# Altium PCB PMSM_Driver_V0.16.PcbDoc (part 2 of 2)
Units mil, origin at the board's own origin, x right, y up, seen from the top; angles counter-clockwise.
Board outline 3933.5 x 3936.3 mil, 2 copper layers (Top Layer, Bottom Layer); 174 components, 117 nets, 508 pads, 484 vias.
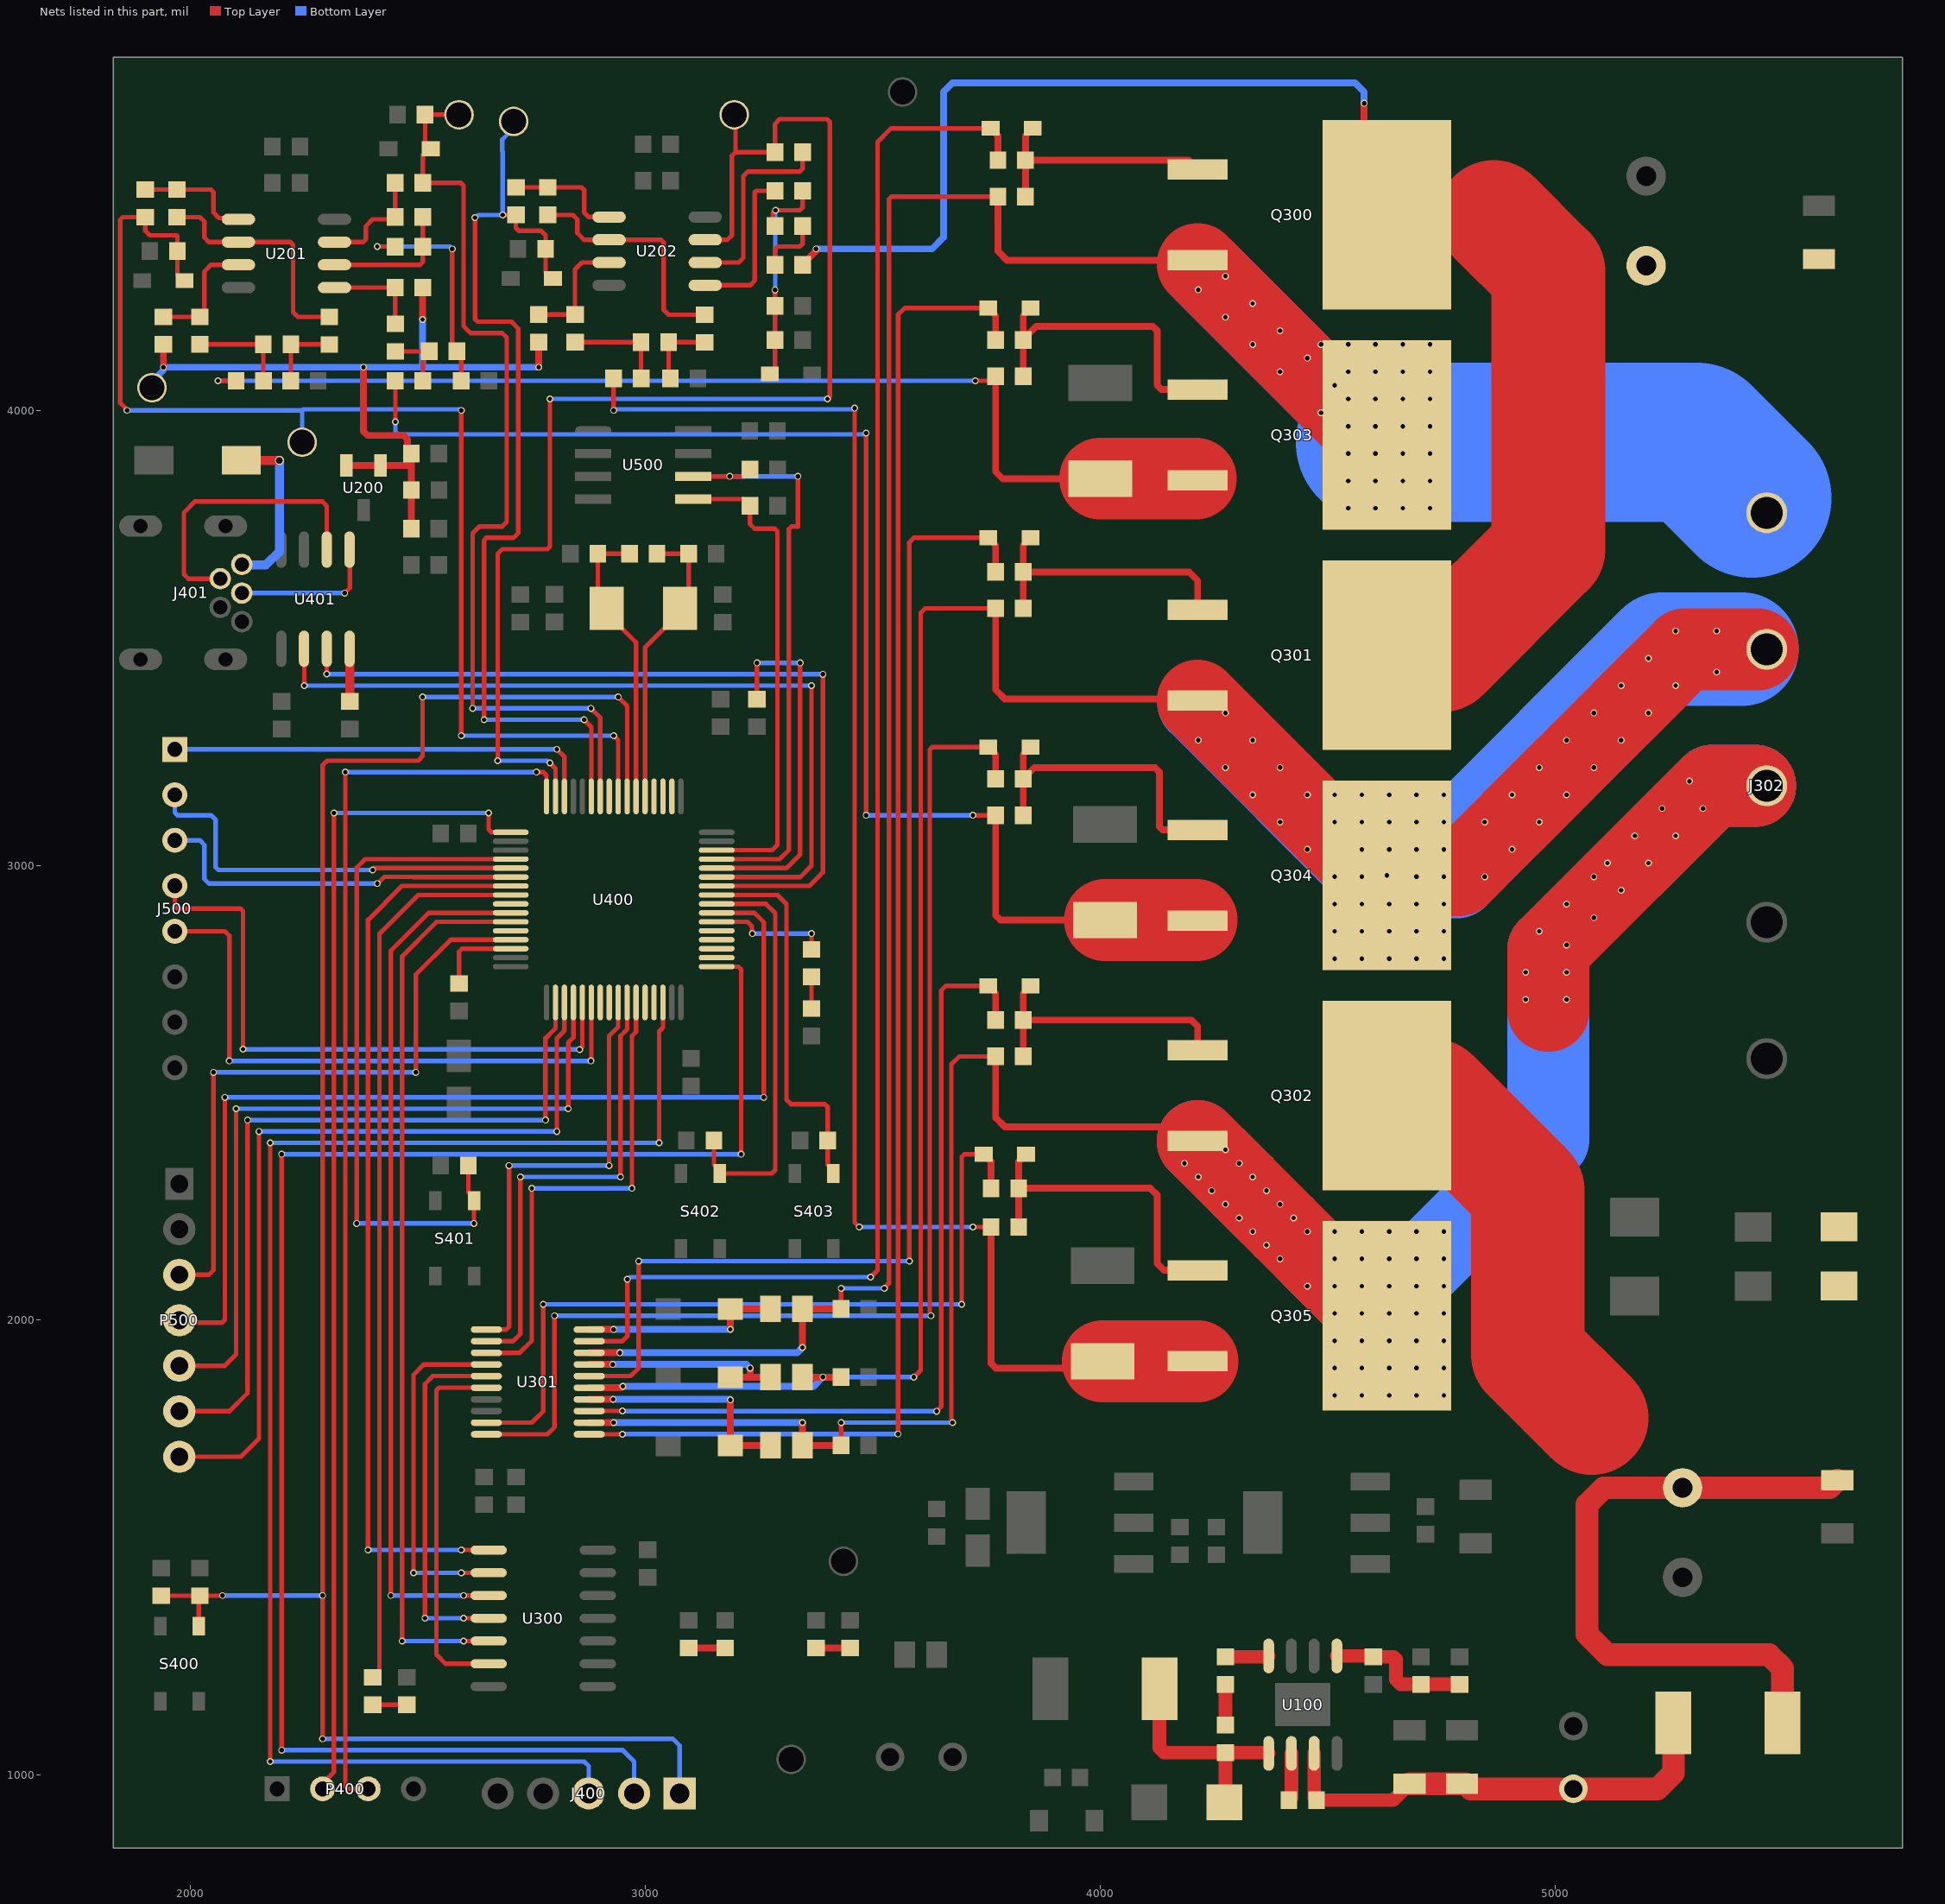
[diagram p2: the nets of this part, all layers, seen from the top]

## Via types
v1: diameter 15, hole 10, Top Layer to Bottom Layer, 465 vias
v2: diameter 30, hole 25, Top Layer to Bottom Layer, 11 vias
v3: diameter 24, hole 12, Top Layer to Bottom Layer, 4 vias
v4: diameter 20, hole 15, Top Layer to Bottom Layer, 3 vias
v5: diameter 30, hole 20, Top Layer to Bottom Layer, 1 vias

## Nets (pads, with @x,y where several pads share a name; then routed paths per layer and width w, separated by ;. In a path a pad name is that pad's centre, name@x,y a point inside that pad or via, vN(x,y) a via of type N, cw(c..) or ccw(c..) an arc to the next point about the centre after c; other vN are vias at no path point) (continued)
EG-VS1: C304.2 J302.1 Q300.3 Q303.4 R303.1 R306.2 U301.18 | length 5971.6
  Top Layer w10: R306.2@3429.68,2025 3429.68,2069.68 v1(3430,2070) ; v1(3525,2070) 3525,2071.35 3535,2081.35 3535,4464.14 3540.86,4470 R303.1@3774.69,4470
  Top Layer w15: U301.18@2876.06,1928.54 v1(2943.54,1928.54) ; v1(3345,1940) v1(3345,1940) C304.2@3345.04,2025 R306.2@3429.68,2025 ; R303.1@3774.69,4470 3774.69,4350.31 3795,4330 Q300.3@4213.8,4330
  Top Layer w180: Q300.3@4213.8,4321.2 4589,3946 Q303.4@4630,3946
  Bottom Layer w10: v1(3430,2070) v1(3525,2070)
  Bottom Layer w15: v1(2943.54,1928.54) 3333.54,1928.54 v1(3345,1940)
  Bottom Layer w180: 4229.8,4305.2 4605,3930
  Bottom Layer w350: 4605,3930 5310,3930 5432.5,3807.5
  other v1: 4545,3785 4605,3785 4665,3785 4725,3785 4545,3845 4605,3845 4665,3845 4725,3845 4545,3905 4605,3905 4665,3905 4725,3905 4545,3965 4605,3965 4665,3965 4725,3965 4485,3995 4545,4025 4605,4025 4665,4025 4725,4025 4515,4055 4395,4085 4545,4085 4605,4085 4665,4085 4725,4085 4455,4115 4335,4145 4485,4145 4545,4145 4605,4145 4665,4145 4725,4145 4395,4175 4275,4205 4335,4235 4215,4265 4275,4295
EG-VS2: C306.2 J302.2 Q301.3 Q304.4 R304.1 R307.2 U301.15 | length 6433.2
  Top Layer w10: v1(3590,1875) 3605,1890 3605,3555 3615,3565 R304.1@3769.69,3565
  Top Layer w15: U301.15@2876.06,1851.77 2946.91,1851.77 v1(2950,1854.86) ; C306.2@3345.04,1875 v1(3390,1875) R307.2@3429.68,1875 ; R304.1@3769.69,3565 3769.69,3386.12 3790,3365.8 4210,3365.8 Q301.3@4213.8,3362
  Top Layer w180: Q301.3@4213.8,3362 4317.9,3257.9 4377.9,3197.9 4437.9,3137.9 4497.9,3077.9 4597.8,2978 v1(4630,2978) 4695,2978 4788,2978 4875,3065 4935,3125 4995,3185 5055,3245 5115,3305 5175,3365 5285,3475 J302.2@5445,3475
  Bottom Layer w10: v1(3390,1875) v1(3590,1875)
  Bottom Layer w15: v1(2950,1854.86) 3369.86,1854.86 v1(3390,1875)
  Bottom Layer w180: 4215.02,3357.98 4599.02,2973.98 4783.98,2973.98
  Bottom Layer w250: 4783.98,3023.98 5235,3475 5410,3475
  other v1: 4515,2795 4575,2795 4635,2795 4695,2795 4755,2795 4515,2855 4575,2855 4635,2855 4695,2855 4755,2855 4515,2915 4575,2915 4635,2915 4695,2915 4755,2915 4515,2975 4575,2975 4695,2975 4755,2975 4845,2975 4455,3035 4575,3035 4635,3035 4695,3035 4755,3035 4905,3035 4395,3095 4515,3095 4575,3095 4635,3095 4695,3095 4755,3095 4845,3095 4965,3095 4335,3155 4455,3155 4515,3155 4575,3155 4635,3155 4695,3155 4755,3155 4905,3155 5025,3155 4275,3215 4395,3215 4965,3215 5085,3215 4215,3275 4335,3275 5025,3275 5145,3275 4275,3335 5085,3335 5205,3335 5145,3395 5265,3395 5355,3425 5205,3455 5265,3515 5355,3515
EG-VS3: C307.2 J302.3 Q302.3 Q305.4 R305.1 R308.2 U301.12 | length 5818.7
  Top Layer w10: R308.2@3429.68,1725 3429.68,1774.68 v1(3430,1775) ; v1(3675,1775) 3672.5,1777.5 3672.5,2562.5 3690,2580 R305.1@3769.69,2580
  Top Layer w15: U301.12@2876.06,1775 v1(2930,1775) ; v1(3345,1775) C307.2@3345.04,1725 C307.2@3345.04,1725 R308.2@3429.68,1725 ; R305.1@3769.69,2580 3769.69,2445.31 3790,2425 4182.8,2425 Q302.3@4213.8,2394
  Top Layer w180: Q302.3@4213.8,2394 4283.9,2323.9 4343.9,2263.9 4403.9,2203.9 4493.9,2113.9 4597.8,2010 Q305.4@4630,2010 ; 4985,2680 4985,2815 5345,3175 J302.3@5440,3175
  Bottom Layer w10: v1(3430,1775) v1(3675,1775)
  Bottom Layer w15: v1(2930,1775) v1(3345,1775)
  Bottom Layer w180: 4213.8,2394 4253.9,2353.9 4313.9,2293.9 4403.9,2203.9 4523.9,2083.9 4597.8,2010 4985,2397.2 4985,2815 5345,3175 J302.3@5440,3175
  other v1: 4515,1835 4575,1835 4635,1835 4695,1835 4755,1835 4515,1895 4575,1895 4635,1895 4695,1895 4755,1895 4515,1955 4575,1955 4635,1955 4695,1955 4755,1955 4515,2015 4575,2015 4635,2015 4695,2015 4755,2015 4455,2075 4515,2075 4575,2075 4635,2075 4695,2075 4755,2075 4395,2135 4515,2135 4575,2135 4635,2135 4695,2135 4755,2135 4365,2165 4335,2195 4455,2195 4515,2195 4575,2195 4635,2195 4695,2195 4755,2195 4305,2225 4425,2225 4275,2255 4395,2255 4245,2285 4365,2285 4215,2315 4335,2315 4185,2345 4305,2345 4275,2375 4935,2705 5025,2705 4935,2765 5025,2765 5025,2825 4965,2855 5085,2885 5025,2915 5145,2945 5085,2975 5115,3005 5205,3005 5175,3065 5265,3065 5235,3125 5325,3125 5295,3185
HO1: D300.2 R300.1 U301.19 | length 3589.4
  Top Layer w10: U301.19@2876.06,1954.13 2949.13,1954.13 2960,1965 v1(2960,2090) ; v1(3495,2095) 3510,2110 3510,4590 3540,4620 D300.2@3758.54,4620
  Top Layer w15: D300.2@3758.54,4620 3774.69,4603.86 R300.1@3774.69,4550
  Bottom Layer w10: v1(2960,2090) 2961.35,2090 2966.35,2095 v1(3495,2095)
HO2: D301.2 R301.1 U301.16 | length 2785.6
  Top Layer w10: U301.16@2876.06,1877.36 2940.54,1877.36 2940.61,1877.43 2967.43,1877.43 2985,1895 v1(2985,2130) ; v1(3580,2130) 3580,3710 3590,3720 D301.2@3753.54,3720
  Top Layer w15: D301.2@3753.54,3720 3769.69,3703.86 R301.1@3769.69,3645
  Bottom Layer w10: v1(2985,2130) v1(3580,2130)
HO3: D302.2 R302.1 U301.13 | length 1882.7
  Top Layer w10: U301.13@2876.06,1800.59 v1(2949.41,1800.59) ; v1(3640,1800) 3650,1810 3650,2725 3660,2735 D302.2@3753.54,2735
  Top Layer w15: D302.2@3753.54,2735 3769.69,2718.86 R302.1@3769.69,2660
  Bottom Layer w10: v1(2949.41,1800.59) 2950,1800 v1(3640,1800)
HSE_IN: C400.2 OSC400.1 R401.1 U400.5 | length 642.7
  Top Layer w10: U400.5@2998.9,3151.37 2998.9,3478.34 3075.71,3555.15 OSC400.1@3075.71,3564.99 3094.68,3583.97 C400.2@3094.68,3685 R401.1@3025.31,3685
HSE_OUT: C401.2 OSC400.2 R401.2 U400.6 | length 637.7
  Top Layer w10: R401.2@2964.68,3685 C401.2@2895.32,3685 2895.32,3583.97 OSC400.2@2914.29,3564.99 2914.29,3555.15 2979.21,3490.23 U400.6@2979.21,3151.37
LO1: D303.2 R309.1 U301.11 | length 3420.6
  Top Layer w10: U301.11@2876.06,1749.41 v1(2949.41,1749.41) ; v1(3555,1750) 3555,4210 3570,4225 D303.2@3753.54,4225
  Top Layer w15: D303.2@3753.54,4225 3769.69,4208.86 R309.1@3769.69,4155
  Bottom Layer w10: v1(2949.41,1749.41) 2950,1750 v1(3555,1750)
LO2: D304.2 R310.1 U301.10 | length 2681.8
  Top Layer w10: U301.10@2650,1749.41 2784.41,1749.41 2800,1765 v1(2800,2010) ; v1(3627.5,2010) 3625,2012.5 3625,3254.14 3630.86,3260 D304.2@3753.54,3260
  Top Layer w15: D304.2@3753.54,3260 3769.69,3243.86 R310.1@3769.69,3190
  Bottom Layer w10: v1(2800,2010) v1(3627.5,2010)
LO3: D305.2 R311.1 U301.9 | length 1747.2
  Top Layer w10: U301.9@2650,1775 2750,1775 2775,1800 v1(2775,2035) ; v1(3695,2035) 3695,2359.14 3700.86,2365 D305.2@3743.54,2365
  Top Layer w15: D305.2@3743.54,2365 3759.69,2348.86 R311.1@3759.69,2290
  Bottom Layer w10: v1(2775,2035) v1(3695,2035)
MOTOR_AMP-U: Q303.3 R209.1 R312.1 R315.2 | length 2401.2
  Top Layer w10: v1(2060,4065) R209.1@2099.69,4065 ; v1(3725,4065) R312.1@3769.69,4065
  Top Layer w15: R312.1@3769.69,4065 3769.69,3865.31 3785,3850 R315.2@4000,3850 ; Q303.3@4209.8,3850 Q303.3@4213.8,3846
  Top Layer w180: R315.2@4000,3850 Q303.3@4209.8,3850
  Bottom Layer w10: v1(2060,4065) v1(3725,4065)
MOTOR_AMP-V: Q304.3 R211.1 R313.1 R316.2 | length 2943.8
  Top Layer w10: R211.1@2449.69,4065 2450,4064.69 v1(2450,3975) ; v1(3485,3110) v1(3485,3950) ; v1(3720,3110) R313.1@3769.69,3110
  Top Layer w15: R313.1@3769.69,3110 3769.69,2890.31 3780,2880 R316.2@4010,2880 ; Q304.3@4211.8,2880 Q304.3@4213.8,2878
  Top Layer w180: R316.2@4010,2880 Q304.3@4211.8,2880
  Bottom Layer w10: v1(2450,3975) 2450,3953.36 2455.86,3947.5 3481.15,3947.5 3483.65,3950 v1(3485,3950) ; v1(3485,3110) v1(3720,3110)
MOTOR_AMP-W: Q305.3 R223.1 R314.1 R317.2 | length 3460.3
  Top Layer w10: R223.1@2929.69,4070 2930,4069.69 v1(2930,4000) ; v1(3460,4005) 3460,2215 v1(3470,2205) ; v1(3720,2205) R314.1@3759.69,2205
  Top Layer w15: R314.1@3759.69,2205 3759.69,1905.31 3770,1895 3990,1895 R317.2@4005,1910
  Top Layer w180: R317.2@4005,1910 Q305.3@4213.8,1910
  Bottom Layer w10: v1(2930,4000) 2932.5,4002.5 3457.5,4002.5 v1(3460,4005) ; v1(3470,2205) v1(3720,2205)
NetC103_1: C103.1 R100.1 R102.2 U100.5 | length 322.2
  Top Layer w30: U100.5@4520,1262.11 4598.21,1262.11 R102.2@4600,1260.32 4644.68,1260.32 4650,1255 4650,1210 4660.31,1199.69 R100.1@4705,1199.69 C103.1@4790,1199.68
NetC104_1: C104.1 D100.2 L100.1 U100.1 | length 485.7
  Top Layer w30: L100.1@4130,1190 4130,1060 4140.32,1049.68 C104.1@4275,1049.68 ; D100.2@4272.68,940 4275,942.32 C104.1@4275,1049.68 ; U100.1@4370,1047.89 4368.21,1049.68 C104.1@4275,1049.68
NetC104_2: C104.2 R101.1 | length 89.4
  Top Layer w30: C104.2@4275,1110.31 R101.1@4275,1199.69
NetC105_1: C105.1 C106.2 C107.2 L101.2 R103.2 U100.3 | length 1034
  Top Layer w30: U100.3@4470,1047.89 4470,950.32 R103.2@4475.32,945 4643.66,945 C106.2@4680,981.34
  Top Layer w50: C106.2@4680,981.34 C107.2@4795,981.34 4802.68,981.34 4814.02,970 C105.1@5040,970 5225,970 5260,1005 L101.2@5260,1115
NetC207_1: C207.1 R209.2 R210.2 | length 219.9
  Top Layer w10: R210.2@2020,4145 C207.1@2159.68,4145 2159.68,4065.63 R209.2@2160.32,4065
NetC207_2: C207.2 R203.2 R204.2 | length 165.1
  Top Layer w10: R203.2@2219.68,4065 2220.32,4065.63 C207.2@2220.32,4145 2304.68,4145 R204.2@2305,4144.68
NetC208_1: C208.1 R211.2 R212.2 | length 145.8
  Top Layer w10: R212.2@2450,4129.68 2524.37,4129.68 C208.1@2524.68,4130 2524.68,4129.02 2510.32,4114.65 R211.2@2510.32,4065
NetC208_2: C208.2 R205.2 R206.2 | length 504.9
  Top Layer w10: v1(2410,4360) R206.2@2449.68,4360 ; v1(2575,4355) 2575,4140.31 C208.2@2585.32,4130 2594.68,4120.63 R205.2@2594.68,4065
  Bottom Layer w10: v1(2410,4360) 2570,4360 v1(2575,4355)
NetC211_1: C211.1 R223.2 R224.2 | length 225.1
  Top Layer w10: R224.2@2845,4150 C211.1@2990,4150 2990,4070.32 R223.2@2990.32,4070
NetC211_2: C211.2 R217.2 R218.2 | length 161.2
  Top Layer w10: R217.2@3054.68,4070 3050.63,4074.05 C211.2@3050.63,4150 3129.68,4150 R218.2@3130,4149.68
NetC213_2: C213.2 D203.1 R220.2 R221.2 R226.2 | length 503.6
  Top Layer w10: D203.1@3273.54,4080 3284.68,4091.14 R226.2@3284.68,4155 C213.2@3284.68,4230 v1(3284.68,4264.69) v1@3285,4265 ; R220.2@3284.68,4405 3280,4409.68 3280,4434.14 v1(3285.86,4440) 3339.46,4440 3345.31,4445.86 R221.2@3345.31,4482.66
  Bottom Layer w10: v1(3284.68,4264.69) 3285.27,4265.27 3285.27,4439.41 v1(3285.86,4440)
NetC403_2: C403.2 U400.30 | length 186.1
  Top Layer w10: C403.2@2590,2740.32 2590,2810 2596.73,2816.73 U400.30@2703.63,2816.73
NetC404_1: C404.1 U401.8 | length 116
  Top Layer w20: U401.8@2349.2,3476.03 2349.6,3475.63 2349.6,3360.71 C404.1@2350,3360.32
NetD105_K: D105.K R104.2 | length 82.1
  Top Layer w15: R104.2@3095,1279.68 3170,1279.68 D105.K@3175,1284.69
NetD106_K: D106.K R105.2 | length 75
  Top Layer w15: R105.2@3375,1279.68 D106.K@3450,1279.69
NetD300_1: D300.1 Q300.1 R300.2 R303.2 | length 615.5
  Top Layer w15: R303.2@3835.32,4470 R300.2@3835.32,4550 ; D300.1@3851.46,4620 3835.32,4603.86 R300.2@3835.32,4550 ; R300.2@3835.32,4550 Q300.1@4150.01,4550 ; Q300.1@4150.01,4550 4193.8,4550 Q300.1@4213.8,4530 4170.01,4530 Q300.1@4150.01,4550
NetD301_1: D301.1 Q301.1 R301.2 R304.2 | length 617.2
  Top Layer w15: R304.2@3830.32,3565 R301.2@3830.32,3645 ; D301.1@3846.46,3720 3830.32,3703.86 R301.2@3830.32,3645 ; Q301.1@4213.8,3562 4213.8,3626.2 4195,3645 R301.2@3830.32,3645
NetD302_1: D302.1 Q302.1 R302.2 R305.2 | length 603.1
  Top Layer w15: R305.2@3830.32,2580 R302.2@3830.32,2660 ; D302.1@3846.46,2735 3830.32,2718.86 R302.2@3830.32,2660 ; Q302.1@4213.8,2594 4213.8,2646.2 4200,2660 R302.2@3830.32,2660
NetD303_1: D303.1 Q303.1 R309.2 R312.2 | length 680.1
  Top Layer w15: R312.2@3830.32,4075 R309.2@3830.32,4155 R309.2@3830.32,4155.98 ; D303.1@3846.46,4225 3830.32,4208.86 R309.2@3830.32,4155.98 ; Q303.1@4213.8,4046 4134,4046 4125,4055 4125,4175 4115,4185 3859.33,4185 R309.2@3830.32,4155.98
NetD304_1: D304.1 Q304.1 R310.2 R313.2 | length 677.2
  Top Layer w15: R313.2@3830.32,3110 R310.2@3830.32,3190 R310.2@3830.32,3190.98 ; D304.1@3846.46,3260 3830.32,3243.86 R310.2@3830.32,3190.98 ; Q304.1@4213.8,3078 4137,3078 4130,3085 4130,3205 4120,3215 3855.32,3215 3842.11,3201.79 3841.12,3201.79 R310.2@3830.32,3190.98
NetD305_1: D305.1 Q305.1 R311.2 R314.2 | length 722.6
  Top Layer w15: R314.2@3820.32,2205 R311.2@3820.32,2290 ; D305.1@3836.46,2365 3820.32,2348.86 R311.2@3820.32,2290 ; Q305.1@4213.8,2110 4140,2110 4125,2125 4125,2275 4110,2290 R311.2@3820.32,2290
NetD400_1: D400.1 J401.1 | length 379.5
  Top Layer w20: D400.1@2111.16,3890 v4(2195,3890)
  Bottom Layer w20: J401.1@2112.39,3661.49 2113.88,3660 2165,3660 2195,3690 v4(2195,3890)
NetD401_A: D401.A R403.2 | length 69.4
  Top Layer w10: D401.A@3365,2685.32 R403.2@3365,2754.68
NetD402_A: D402.A R404.2 | length 75
  Top Layer w10: R404.2@2400,1154.68 D402.A@2475,1154.68
NetR101_2: R101.2 U100.8 | length 95.7
  Top Layer w30: R101.2@4275,1260.32 4368.21,1260.32 U100.8@4370,1262.11
NetR103_1: R103.1 U100.2 | length 105.1
  Top Layer w30: R103.1@4414.69,945 4420,950.31 U100.2@4420,1047.89
NetR201_1: R201.1 R207.1 U201.1 | length 258.1
  Top Layer w10: R207.1@1900,4485.31 R201.1@1970,4485.31 2044.14,4485.31 2050,4479.46 2050,4435 2062.17,4422.83 2102.17,4422.83 U201.1@2105,4420
NetR201_2: R201.2 R204.1 U201.2 | length 533.2
  Top Layer w10: R201.2@1970,4424.68 2020.32,4424.68 2030,4415 2030,4380 2040,4370 U201.2@2105,4370 2219.14,4370 2225,4364.14 2225,4215.86 2235.54,4205.31 R204.1@2305,4205.31
NetR202_1: R202.1 R208.1 U201.7 | length 251.2
  Top Layer w10: U201.7@2316.22,4370 2379.14,4370 2385,4375.86 2385,4405 2400,4420 2449.68,4420 R208.1@2449.68,4500
NetR202_2: R202.2 R206.1 U201.6 | length 290.7
  Top Layer w10: U201.6@2316.22,4320 2504.46,4320 2510.31,4325.86 R206.1@2510.31,4360 R202.2@2510.31,4420
NetR210_1: R210.1 R213.2 U201.3 | length 264.7
  Top Layer w10: R213.2@1940,4205.63 R210.1@2020,4205.63 2030,4215.63 2030,4305 2045,4320 U201.3@2105,4320
NetR212_1: R212.1 R214.2 U201.5 | length 213.3
  Top Layer w10: U201.5@2316.22,4270 R214.2@2449.68,4270 2449.68,4190.63 R212.1@2450,4190.31
NetR215_1: R215.1 U202.6 | length 441.6
  Top Layer w10: U202.6@3131.22,4325 3205,4325 3215,4335 3215,4515 3225,4525 3339.46,4525 3345.31,4530.86 R215.1@3345.31,4567.66
NetR216_1: R216.1 R222.1 U202.1 | length 261
  Top Layer w10: R222.1@2715,4490.31 R216.1@2785,4490.31 2859.14,4490.31 2865,4484.46 2865,4435 2875,4425 U202.1@2920,4425
NetR216_2: R216.2 R218.1 U202.2 | length 540.3
  Top Layer w10: R216.2@2785,4429.68 2840.32,4429.68 2850,4420 2850,4390 2865,4375 U202.2@2920,4375 3034.14,4375 3040,4369.14 3040,4220.86 3050.54,4210.31 R218.1@3130,4210.31
NetR219_2: R219.2 R220.1 | length 138.8
  Top Layer w10: R219.2@3284.68,4320 3284.68,4354.14 3290.54,4360 3339.46,4360 3345.31,4365.86 R220.1@3345.31,4405
NetR221_1: R221.1 U202.5 | length 353.2
  Top Layer w10: U202.5@3131.22,4275 3230,4275 3240,4285 3240,4479.07 3243.58,4482.66 R221.1@3284.68,4482.66
NetR224_1: R224.1 R225.2 U202.3 | length 260.6
  Top Layer w10: R225.2@2765,4210.63 R224.1@2845,4210.63 2845,4310 2860,4325 U202.3@2920,4325
NetR402_1: R402.1 U400.60 | length 1255.4
  Top Layer w10: U400.60@3156.37,2993.9 3310,2993.9 ; R402.1@3245,3365.31 v1(3245,3445) ; 3310,2993.9 3340,3023.9 ; 3310,2993.9 3340,3023.9 ; 3340,3023.9 v1(3340,3445) 3340,3023.9
  Bottom Layer w10: v1(3245,3445) v1(3340,3445)
NRST: C402.2 J400.5 R400.1 S400.1 U400.7 | length 4474.2
  Top Layer w10: R400.1@1935,1394.69 C402.2@2020,1394.68 ; S400.1@2017.83,1327.68 2017.83,1392.52 C402.2@2020,1394.68 ; v1(2070,1395) 2069.68,1394.68 C402.2@2020,1394.68 ; v1(2290,1080) 2290,3220 2300,3230 2500,3230 2510,3240 v1(2510,3370) ; v1(2940,3370) 2959.53,3350.47 U400.7@2959.53,3151.37
  Bottom Layer w10: v1(2070,1395) v1(2290,1395) ; v1(2290,1080) 3060,1080 3075,1065 J400.5@3075,960 ; v1(2510,3370) v1(2940,3370)
PA0: J500.1 U400.14 | length 950.6
  Top Layer w10: v1(2805,3255) 2821.73,3238.27 U400.14@2821.73,3151.37
  Bottom Layer w10: J500.1@1965,3255 v1(2805,3255)
PA1_ADC1_IN1_BUS_VOLTAGE: R215.2 T203.1 U202.7 U400.15 | length 2926
  Top Layer w10: v1(2675,3230) 2675,3685 2685,3695 2784.14,3695 2790,3700.86 v1(2790,4025) ; v1(2790,3225) 2802.05,3212.95 U400.15@2802.05,3151.37 ; U202.7@3131.22,4375 3180,4375 3190,4385 3190,4560 3197.66,4567.66 ; T203.1@3195,4650 3197.66,4647.34 3197.66,4567.66 ; v1(3400,4025) 3400,4026.35 3405,4031.35 3405,4634.14 3399.14,4640 3295,4640 3284.68,4629.68 R215.2@3284.68,4567.66 3197.66,4567.66
  Bottom Layer w10: v1(2675,3230) 2783.65,3230 2788.65,3225 v1(2790,3225) ; v1(2790,4025) v1(3400,4025) v1@3400.15,4025
PA2_UART2_TX: P400.3 U400.16 | length 2773.2
  Top Layer w10: v1(2340,3205) 2340,975.86 2345.86,970 P400.3@2390,970 ; v1(2760,3205) 2775,3205 2782.01,3197.99 2782.01,3151.72 U400.16@2782.36,3151.37
  Bottom Layer w10: v1(2340,3205) v1(2760,3205)
PA3_UART2_RX: P400.2 U400.17 | length 2582.7
  Top Layer w10: P400.2@2290,970 2290,982.02 2315,1007.02 v1(2315,3115) ; v1(2655,3115) 2655,3078.84 2660.86,3072.99 2703.28,3072.99 U400.17@2703.63,3072.64
  Bottom Layer w10: v1(2315,3115) v1(2655,3115)
PA4_START/STOP_BTN: C406.2 S401.1 U400.20 | length 1518.7
  Top Layer w10: v1(2365,2212.83) 2365,2995 2383.58,3013.58 U400.20@2703.63,3013.58 ; C406.2@2610.32,2340 2610.32,2282.09 2622.83,2269.57 S401.1@2622.83,2262.68 v1(2622.83,2212.83)
  Bottom Layer w10: v1(2365,2212.83) v1(2622.83,2212.83)
PA5: J500.2 U400.21 | length 892.5
  Top Layer w10: v1(2400,2990) 2403.9,2993.9 U400.21@2703.63,2993.9
  Bottom Layer w10: J500.2@1965,3155 1965,3115.86 1970.86,3110 2045,3110 2055,3100 2055,2995.86 2060.86,2990 v1(2400,2990)
PA6: J500.3 U400.22 | length 828
  Top Layer w10: v1(2410,2960) 2411.35,2960 2425.85,2974.5 2490,2974.5 2490.29,2974.21 U400.22@2703.63,2974.21
  Bottom Layer w10: J500.3@1965,3055 2020,3055 2030,3045 2030,2970 2040,2960 v1(2410,2960)
PA7_TIM1_CH1N_UL: U300.1 U400.23 | length 1994.5
  Top Layer w10: v1(2390,1495) 2390,2880 2464.53,2954.53 U400.23@2703.63,2954.53 ; v1(2595,1495) U300.1@2655,1495
  Bottom Layer w10: v1(2390,1495) v1(2595,1495)
PA7_TIM1_CH1N_UL-F: U300.2 U301.4 | length 769.5
  Top Layer w10: v1(2490,1445) 2490,1880 2512.95,1902.95 U301.4@2650,1902.95 ; v1(2595,1445) U300.2@2655,1445
  Bottom Layer w10: v1(2490,1445) v1(2595,1445)
PA8_TIM1_CH1_UH: U301.1 U400.41 | length 993.7
  Top Layer w10: U301.1@2650,1979.72 2694.14,1979.72 2700,1985.58 v1(2700,2340) ; v1(2920,2340) 2920,2625 2939.84,2644.84 U400.41@2939.84,2698.63
  Bottom Layer w10: v1(2700,2340) v1(2920,2340)
PA9_TIM1_CH2_VH: U301.2 U400.42 | length 1036.2
  Top Layer w10: U301.2@2650,1954.13 2709.13,1954.13 2725,1970 v1(2725,2315) ; v1(2945,2315) 2945,2625 2959.53,2639.53 U400.42@2959.53,2698.63
  Bottom Layer w10: v1(2725,2315) v1(2945,2315)
PA10_TIM1_CH3_WH: U301.3 U400.43 | length 1078.4
  Top Layer w10: U301.3@2650,1928.54 2723.54,1928.54 2750,1955 v1(2750,2290) ; v1(2970,2290) 2970,2625 2979.21,2634.21 U400.43@2979.21,2698.63
  Bottom Layer w10: v1(2750,2290) v1(2970,2290)
PA11: U400.44
PA12: U400.45
PA15: U400.50
PB0_TIM1_CH2N_VL: U300.3 U400.26 | length 1930.4
  Top Layer w10: v1(2440,1395) 2440,2812.37 2523.1,2895.47 U400.26@2703.63,2895.47 ; v1(2600,1395) U300.3@2655,1395
  Bottom Layer w10: v1(2440,1395) v1(2600,1395)
PB0_TIM1_CH2N_VL-F: U300.4 U301.5 | length 797.2
  Top Layer w10: v1(2515,1345) 2515,1860 2532.36,1877.36 U301.5@2650,1877.36 ; v1(2600,1345) U300.4@2655,1345
  Bottom Layer w10: v1(2515,1345) v1(2600,1345)
PB1_TIM1_CH3N_WL: U300.5 U400.27 | length 1965
  Top Layer w10: v1(2465,1295) 2465,2800 2540.79,2875.79 U400.27@2703.63,2875.79 ; v1(2600,1295) U300.5@2655,1295
  Bottom Layer w10: v1(2465,1295) v1(2600,1295)
PB1_TIM1_CH3N_WL-F: U300.6 U301.6 | length 816.4
  Top Layer w10: U301.6@2650,1851.77 2545.86,1851.77 2540,1845.91 2540,1265.36 2560.36,1245 U300.6@2655,1245
PB2: U400.28
PB3_I2C2_SDA: P500.4 U400.55 | length 2275.7
  Top Layer w10: P500.4@1975,2000 1980,1995 2069.14,1995 2075,2000.86 v1(2075,2490) ; U400.55@3156.37,2895.47 3239.53,2895.47 3260,2875 v1(3260,2490)
  Bottom Layer w10: v1(2075,2490) v1(3260,2490)
PB4_USER_BTN: C407.2 S402.1 U400.56 | length 904.7
  Top Layer w10: C407.2@3150.32,2395 3150.32,2342.09 3162.83,2329.57 S402.1@3162.83,2322.68 3277.68,2322.68 3285,2330 3285,2895 3264.84,2915.16 U400.56@3156.37,2915.16
PB5_USER_BTN: C408.2 S403.1 U400.57 | length 840.4
  Top Layer w10: U400.57@3156.37,2934.84 3290.16,2934.84 3310,2915 3310,2485 3320,2475 3394.46,2475 3400.32,2469.14 C408.2@3400.32,2395 3400.32,2342.09 3412.83,2329.57 S403.1@3412.83,2322.68
PB6_UART1_TX: U400.58 U401.7 | length 2305.8
  Top Layer w10: v1(2299.2,3420.8) U401.7@2299.2,3476.03 ; U400.58@3156.37,2954.53 3360,2954.53 ; 3360,2954.53 3385,2979.53 3385,2980 3390,2985 v1(3390,3420) 3390,2984.53 3360,2954.53
  Bottom Layer w10: v1(2299.2,3420.8) 2300,3420 v1(3390,3420)
PB7_UART1_RX: U400.59 U401.6 | length 2242.3
  Top Layer w10: U401.6@2249.2,3476.03 2250,3475.24 v1(2250,3395) ; U400.59@3156.37,2974.21 3340,2974.21 ; 3340,2974.21 3365,2999.21 ; 3340,2974.21 3365,2999.21 ; 3365,2999.21 v1(3365,3395) 3365,2999.21
  Bottom Layer w10: v1(2250,3395) v1(3365,3395)
PB8_I2C1_SCL: R500.1 U400.61 U500.6 | length 1286.4
  Top Layer w10: U500.6@3105,3855 v1(3185,3855) 3215.67,3855 3229.69,3869.02 R500.1@3229.69,3870 ; U400.61@3156.37,3013.58 3295,3013.58 3315,3033.58 3315,3739.14 3320.86,3745 3335,3745 v1(3335,3855)
  Bottom Layer w10: v1(3185,3855) v1(3335,3855)
PB9_I2C1_SDA: R501.1 U400.62 U500.5 | length 1065.8
  Top Layer w10: U500.5@3105,3805 3215.67,3805 3229.69,3790.98 R501.1@3229.69,3790 3229.69,3750.31 3240,3740 3284.14,3740 3290,3734.14 3290,3045 3278.27,3033.27 U400.62@3156.37,3033.27
PB10_I2C2_SCL: P500.3 U400.29 | length 1421.5
  Top Layer w10: P500.3@1975,2100 2040,2100 2050,2110 v1(2050,2545) ; v1(2495,2545) 2495,2760 2571.42,2836.42 U400.29@2703.63,2836.42
  Bottom Layer w10: P500.3@1975,2100 P500.3@1980,2105 ; v1(2050,2545) v1(2495,2545)
PB13_SPI2_SCK: P500.6 U400.34 | length 1689.3
  Top Layer w10: P500.6@1975,1800 2085,1800 2125,1840 v1(2125,2440) ; v1(2780,2440) 2780,2620 2802.05,2642.05 U400.34@2802.05,2698.63
  Bottom Layer w10: v1(2125,2440) v1(2780,2440)
PB14_SPI2_MISO: P500.7 U400.35 | length 1812.1
  Top Layer w10: P500.7@1975,1700 2110,1700 2150,1740 v1(2150,2415) ; v1(2805,2415) 2805,2620 2821.73,2636.73 U400.35@2821.73,2698.63
  Bottom Layer w10: v1(2150,2415) v1(2805,2415)
PB15_SPI2_SNSS: P500.5 U400.36 | length 1646.5
  Top Layer w10: P500.5@1975,1900 2075,1900 2100,1925 v1(2100,2465) ; v1@2830,2462.22 2830,2610 2841.42,2621.42 U400.36@2841.42,2698.63
  Bottom Layer w10: v1(2100,2465) v1(2830,2465)
PC0_ADC1_IN10_CURR_U: C209.2 D200.1 R207.2 T201.1 U400.8 | length 2689.3
  Top Layer w10: v1(1860,4000) 1860,4001.35 1845,4016.35 1845,4418.83 1850.86,4424.68 R207.2@1900,4424.68 1900,4395 1910,4385 1969.14,4385 1970.63,4383.51 C209.2@1970.63,4350 1970.63,4297.48 1983.11,4285 D200.1@1986.46,4285 ; v1(2595,3285) v1(2595,4000) ; v1(2930,3285) 2939.84,3275.16 U400.8@2939.84,3151.37
  Bottom Layer w10: v1(1860,4000) 2245,4000 ; T201.1@2245,3930 2245,4000 ; v1(2595,3285) v1(2930,3285) ; v1(2595,4000) 2592.5,4002.5 2247.5,4002.5 2245,4000
PC1: U400.9
PC2_ADC1_IN12_CURR_V: C210.2 D201.1 R208.2 T202.1 U400.10 | length 2045.3
  Top Layer w10: D201.1@2510.32,4560.75 R208.2@2510.32,4500 2594.14,4500 2600,4494.14 2600,4185 2615,4170 2685,4170 2695,4160 2695,3755 2685,3745 2635,3745 2620,3730 v1(2620,3345) ; D201.1@2515.32,4584.25 C210.2@2515.32,4650 T202.1@2590,4650 ; v1(2880,3345) 2900.47,3324.53 U400.10@2900.47,3151.37
  Bottom Layer w10: v1(2620,3345) v1(2880,3345)
PC3_ADC1_IN13_CURR_W: C212.2 D202.1 R222.2 T204.1 U400.11 | length 2160.7
  Top Layer w10: v1(2625,4423.83) 2625,4200.86 2630.86,4195 2705,4195 2720,4180 2720,3730 2710,3720 2650,3720 2645,3715 v1(2645,3320) ; v1(2686,4429.68) R222.2@2715,4429.68 2715,4400.86 2720.86,4395 2770,4395 2780.32,4384.69 C212.2@2780.32,4355 2780.32,4302.8 2793.11,4290 D202.1@2796.46,4290 ; v1(2865,3320) 2880.79,3304.21 U400.11@2880.79,3151.37
  Bottom Layer w10: v1(2625,4423.83) 2626.35,4423.83 2632.21,4429.68 v1(2686,4429.68) 2686,4569 2685,4570 2685,4595.12 2710,4620.12 T204.1@2710,4635 ; v1(2645,3320) v1(2865,3320)
PC4_FLASH_LED: R404.1 U400.24 | length 1965.1
  Top Layer w10: R404.1@2400,1215.31 2400.98,1215.31 2414.29,1228.62 2414.29,1229.61 2415,1230.31 2415,2849.68 2500.16,2934.84 U400.24@2703.63,2934.84
PC5: U400.25
PC6_UART6_TX: J500.4 U400.37 | length 1348.7
  Top Layer w10: J500.4@1965,2955 1965,2910.86 1970.86,2905 2109.14,2905 2115,2899.14 v1(2115,2596.04) ; v1(2855,2595) 2861.1,2601.1 U400.37@2861.1,2698.63
  Bottom Layer w10: v1(2115,2596.04) 2115.52,2595.52 2854.48,2595.52 v1(2855,2595)
PC7_UART6_RX: J500.5 U400.38 | length 1322
  Top Layer w10: J500.5@1965,2855 2075,2855 2085,2845 v1(2085,2570) ; v1@2880.79,2570.79 U400.38@2880.79,2698.63
  Bottom Layer w10: v1(2085,2570) v1(2880,2570)
PC8: U400.39
PC9: U400.40
PC10: U400.51
PC11: U400.52
PC12: U400.53
PC13: U400.2
PC14: U400.3
PC15: U400.4
PD2_FAULT_LED: R403.1 U400.54 | length 262.8
  Top Layer w10: U400.54@3156.37,2875.79 3224.21,2875.79 3234.04,2865.96 3234.04,2850.96 v1(3235,2850) ; R403.1@3365,2815.31 v1(3365,2850)
  Bottom Layer w10: v1(3235,2850) v1(3365,2850)
POWER: C300.1 C301.1 C302.1 C303.1 D102.1 D104.1 L101.1 Q300.4 Q301.4 Q302.4 R219.1 | length 5529.6
  Top Layer w15: R219.1@3345.31,4320 3345.31,4320.98 3375,4350.67 v1(3375,4355) ; v1(4580,4675) 4580,4480 Q300.4@4630,4430 ; Q302.4@4619,2505 Q302.4@4630,2494
  Top Layer w50: L101.1@5500,1115 5500,1235 5470,1265 5115,1265 5070,1310 5070,1595 5106.85,1631.85 C303.1@5280,1631.85 5603.19,1631.85 C302.1@5620,1648.66
  Top Layer w250: Q302.4@4630,2494 4731,2494 4940,2285 4940,1925 5080,1785 ; Q301.4@4630,3462 4752,3462 4985,3695 4985,4305 4865,4425
  Bottom Layer w15: v1(3375,4355) 3630,4355 3655,4380 3655,4700 3675,4720 4560,4720 4580,4700 v1(4580,4675)
SWCLK: J400.4 U400.49 | length 3637.9
  Top Layer w10: v1(2200,1055) v1(2200,2365) ; U400.49@3156.37,2777.36 3204.14,2777.36 3210,2771.5 v1(3210,2365)
  Bottom Layer w10: v1(2200,1055) 2950,1055 2975,1030 J400.4@2975,960 ; v1(2200,2365) v1(3210,2365)
SWDIO: J400.3 U400.46 | length 3291.2
  Top Layer w10: v1(2175,1030) v1(2175,2390) ; v1(3030,2390) 3030,2635 3038.27,2643.27 U400.46@3038.27,2698.63
  Bottom Layer w10: v1(2175,1030) 2865,1030 2875,1020 J400.3@2875,960 ; v1(2175,2390) v1(3030,2390)
USB_D+: J401.3 U401.1 | length 326.7
  Top Layer w10: v1(2338.5,3598.5) 2350,3610 2350,3693.17 U401.1@2349.2,3693.97
  Bottom Layer w10: J401.3@2112.39,3598.5 v1(2338.5,3598.5)
USB_D-: J401.2 U401.2 | length 643.8
  Top Layer w10: J401.2@2065,3630 1995,3630 1985,3640 1985,3775 2010,3800 2289.14,3800 2299.2,3789.94 U401.2@2299.2,3693.97
VB-EG2133-U: C304.1 D306.1 U301.20 | length 444
  Top Layer w15: U301.20@2876.06,1979.72 v1(2929.72,1979.72) ; v1(3186.61,1980) D306.1@3186.61,2025 C304.1@3274.96,2025
  Bottom Layer w15: v1(2929.72,1979.72) 3186.33,1979.72 v1(3186.61,1980)
VB-EG2133-V: C306.1 D307.1 U301.17 | length 465
  Top Layer w15: U301.17@2876.06,1902.95 v1(2927.95,1902.95) ; D307.1@3186.61,1875 3229,1875 3230,1876 v1(3230,1895) ; 3230,1875 C306.1@3274.96,1875
  Bottom Layer w15: v1(2927.95,1902.95) 3222.05,1902.95 v1(3230,1895)
VB-EG2133-W: C307.1 D308.1 U301.14 | length 499.4
  Top Layer w15: U301.14@2876.06,1826.18 v1(2928.82,1826.18) ; v1(3186.61,1825) D308.1@3186.61,1725 C307.1@3274.96,1725
  Bottom Layer w15: v1(2928.82,1826.18) 3185.43,1826.18 v1(3186.61,1825)
VCC1.25REF: C205.2 C206.2 R200.2 R213.1 R214.1 R225.1 T200.1 U200.1 U200.2 | length 1748.8
  Top Layer w15: v1(1940,4095) R213.1@1940,4145 ; U200.2@2342.6,3879.21 U200.1@2417.4,3879.21 2484.21,3879.21 2485,3880 ; v1(2380,4095) 2380,3953.79 2388.79,3945 2468.01,3945 2476.79,3936.21 2476.79,3913.21 C205.2@2485,3905 2484.21,3904.21 2485,3903.43 2485,3880 ; R200.2@2485,3740 2485,3825 2485,3880 ; v1(2510,4200) 2510,4269.69 R214.1@2510.31,4270 ; v1(2765,4095) R225.1@2765,4150
  Bottom Layer w15: T200.1@1915,4050 1915,4063.53 1940,4088.53 v1(1940,4095) v1(2380,4095) 2510,4095 ; v1(2510,4200) 2510,4095 ; v1(2765,4095) 2510,4095
pads on no net: J401.0 J401.4 S400.2 S400.3 S401.2 S401.4 S402.2 S402.4 S403.2 S403.4 U100.6 U100.7 U100.9 U300.8 U300.9 U300.10 U300.11 U300.12 U300.13 U400.33 U401.4
copper on no net:
  other v3: 4425.32,1135.31 4464.69,1135.31 4425.32,1174.68 4464.69,1174.68

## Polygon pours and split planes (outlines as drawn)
DGND on Top Layer "DGND_L01_P000" (solid, remove dead copper, pour order 0): 3630,1735 3645,1720 4980,1720 5010,1690 5010,1280 5035,1255 5720,1255 5740,1275 5740,4540 5705,4575 5520,4575 5520,4715 5485,4750 3640,4750 3630,4740
DGND on Top Layer "DGND_L01_P003" (solid, remove dead copper, pour order 3): 1850,1070 1860,1060 2035,1060 2050,1045 2045,1040 2045,870 2050,865 5330,865 5335,870 5335,1200 5315,1220 4880,1220 4870,1230 4870,1670 4860,1680 3585,1680 3580,1685 3580,4745 3575,4750 2065,4750 2055,4740 2055,4580 2045,4570 1855,4570 1850,4565
DGND on Bottom Layer "DGND_L02_P002" (solid, remove dead copper, pour order 2): 1850,1070 1860,1060 2035,1060 2050,1045 2045,1040 2045,870 2050,865 5330,865 5335,870 5335,1200 5315,1220 4880,1220 4870,1230 4870,1670 4860,1680 3585,1680 3580,1685 3580,4745 3575,4750 2065,4750 2055,4740 2055,4580 2045,4570 1855,4570 1850,4565
DGND on Bottom Layer "DGND_L02_P001" (solid, remove dead copper, pour order 1): 3630,1735 3645,1720 4980,1720 5010,1690 5010,1280 5035,1255 5720,1255 5740,1275 5740,4540 5705,4575 5520,4575 5520,4715 5485,4750 3640,4750 3630,4740

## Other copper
Top Layer:
  rectangle net DGND: 3890,2040 4075,2215
  rectangle net DGND: 3885,3015 4080,3185
  rectangle net DGND: 3890,3985 4070,4155
  region net POWER: 5560.07,1565.17 4960,1565.17 4960,1930 5570.07,1930
  region net POWER: 5565,1607.5 5565,4222.5 4500,4222.5 4500,4637.5 5025,4637.5 5025,4422.5 5055,4392.5 5740,4392.5 5740,1607.5
  region net 75V-PVDC: 5275,2647.5 5275,2137.5 5095,2137.5 5095,1972.5 5525,1972.5 5525,2647.5
Bottom Layer:
  rectangle net EG-VS1: 4480,3740 4795,4160
  rectangle net EG-VS3: 4485,1800 4800,2220
  rectangle net EG-VS2: 4490,2770 4805,3190
  region net EG-VS3: 4485,2680 4495,2670 4495,2125 5055,2125 5075,2145 5075,2680
  region net EG-VS2: 4490,3595 4490,3085 5015,3085 5342.5,3412.5 5360,3395 5525,3395 5525,3595

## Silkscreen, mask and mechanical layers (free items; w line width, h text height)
Top Overlay:
  circle w10: c1941.06,953.15 r98.43
  circle w10: c5649.72,953.15 r98.43
  circle w10: c5649.72,4661.81 r98.43
  circle w10: c1941.06,4661.81 r98.43
  text "100*100" at 1860,4810.78 h70
  text "W" at 2766.95,4617.04 h70
  text "GND" at 3479.49,4606.41 h90
  text "V" at 2567.02,4562.04 h70
  text "1.25V" at 1875,3965.78 h70
  text "U" at 2230,3835.78 h70
  text "U" at 5130.32,3746.22 h110
  text "V" at 5121.26,3430 h110
  text "A0" at 2160.64,3219.83 h70
  text "A5" at 2160.64,3121.97 h70
  text "W" at 5095,3115 h110
  text "A6" at 2160.64,3024.12 h70
  text "C6" at 2160.64,2926.26 h70
  text "U6" at 2270.64,2879.83 h70
  text "-" at 5151.62,2848.04 h140
  text "C7" at 2160.64,2828.4 h70
  text "5V" at 2160.64,2730.55 h70
  text "3V3" at 2160.64,2632.69 h70
  text "故障指示" at 3405.06,2631.35 h70
  text "DG" at 2160.64,2534.83 h70
  text "+" at 5135.04,2527.56 h120
  text "5V" at 2105.64,2290.78 h70
  text "B5" at 3450,2235.78 h70
  text "B4" at 2930,2230 h70
  text "GD" at 2105.64,2188.12 h70
  text "B10_SCL" at 2105.64,2097.13 h70
  text "A4" at 2550.64,2019.05 h70
  text "B3_SDA" at 2105.64,1994.47 h70
  text "B15_SNSS" at 2105.64,1891.81 h70
  text "B13_SCK" at 2105.64,1789.15 h70
  text "B14_MISO" at 2105.64,1686.49 h70
  text "11V" at 3300,1440 h70
  text "运行" at 2330.06,1271.09 h70
  text "3V3指示" at 2980,1161.73 h80
  text "11V指示" at 3245,1161.73 h80
  text "3V3" at 2113.53,1106.79 h70
  text "3V3" at 2610,1095.78 h70
  text "GD" at 2720,1095.78 h70
  text "复位" at 1915,1071.09 h70
  text "GND" at 3244.49,931.41 h90
Bottom Overlay:
  text "光伏水泵控制板" at 4206.9,2664.43 h120
  text "20230215_V0.16" at 4205.11,2516.33 h120
Mechanical 1:
  circle w10: c1941.06,953.15 r62.99
  circle w10: c5649.72,953.15 r62.99
  circle w10: c5649.72,4661.81 r62.99
  circle w10: c1941.06,4661.81 r62.99
  lines w10: 1825,4775.51 1825,840 5762.01,840 ; 1826.5,4777.01 5763.5,4777.01 5763.5,840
